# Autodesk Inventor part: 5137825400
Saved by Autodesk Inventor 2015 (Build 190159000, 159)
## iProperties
Created: 2020-07
Part Number: 5137825400
Checked By: TraceParts S.A.
Material: Generic
Catalog Web Link: www.traceparts.com
Document SubType Name: Modeling
Designer: TraceParts
Density: 1 g/cm^3
Appearance: Default
Company: TraceParts S.A.
Author: TraceParts
REFERENCE: 5137825400
DESIGN: CVAB/4-1400/250 N D 0,11KW (230V) 50Hz - 5137825400
SUPPLIER: Soler & Palau
TraceParts.PartNumber: 10-14122018-105188
TraceParts.PartTitle: CVAT-N
TraceParts.InstanceId: 10-14122018-105188EZ6VMR99ZZNEGX5N88AIEEZD6
TraceParts.PartStatus: Published
TraceParts.PartVersion: 1.0.4
TRACEPARTS: TRACEPARTS
TraceParts.PartLanguage: en
TraceParts.ClassPath: SOLER_PALAU:10-14122018-105188
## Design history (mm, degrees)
feature "5137825400"
body "Solid1"
